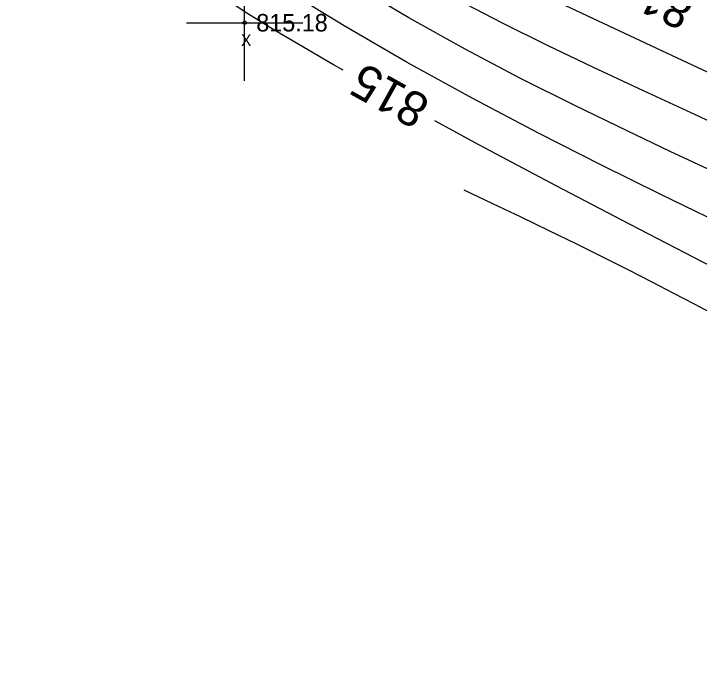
# Model space of a CAD drawing. Extents: x 1378535 to 1380697, y 997729 to 1000024.
# Drawn here: x 1379860 to 1379918.9, y 998571.5 to 998627.2 of the extents above; entities that cross this region are included whole.
import ezdxf

# ---------------------------------------------------------------- set-up
doc = ezdxf.new("R2010")
doc.units = 0
for name, color, linetype in [('RD_DTM_Major1', 7, 'Continuous'), ('RD_DTM_Major1_Lbl', 7, 'Continuous'), ('RD_DTM_Minor1', 7, 'Continuous'), ('RD_EX_Misc', 7, 'Continuous'), ('RD_EX_Misc_txCode', 7, 'Continuous'), ('RD_EX_TX_Misc_ELEV', 7, 'Continuous'), ('RD_SMD_Locator', 7, 'Continuous')]:
    doc.layers.add(name, color=color, linetype=linetype)

msp = doc.modelspace()

# ---------------------------------------------------------------- linework, layer by layer
at = {"layer": 'RD_DTM_Major1'}
for points in [[(1379888.299, 998622.362), (1379887.483, 998622.818), (1379882.346, 998625.829), (1379881.104, 998626.592), (1379879.945, 998627.322), (1379878.849, 998628.03), (1379877.798, 998628.726), (1379876.772, 998629.421), (1379875.752, 998630.124), (1379873.245, 998631.897), (1379870.675, 998633.765), (1379868.053, 998635.71), (1379865.393, 998637.713), (1379862.708, 998639.753), (1379860.01, 998641.813)], [(1379984.414, 998571.472), (1379984.005, 998571.536), (1379982.737, 998571.823), (1379981.492, 998572.144), (1379980.256, 998572.502), (1379979.016, 998572.902), (1379977.757, 998573.347), (1379976.466, 998573.841), (1379969.293, 998577.101), (1379961.379, 998581.317), (1379953.163, 998586.076), (1379945.086, 998590.961), (1379937.588, 998595.557), (1379931.108, 998599.448), (1379928.857, 998600.742), (1379926.767, 998601.902), (1379924.762, 998602.981), (1379922.764, 998604.028), (1379920.697, 998605.095), (1379918.483, 998606.233), (1379912.891, 998609.124), (1379906.6, 998612.417), (1379900.005, 998615.923), (1379896.173, 998618.003)]]:
    msp.add_lwpolyline(points, dxfattribs=at)
at = {"layer": 'RD_DTM_Minor1'}
for points in [[(1379920.029, 998613.667), (1379916.391, 998615.378), (1379912.69, 998617.129), (1379908.191, 998619.307), (1379903.548, 998621.639), (1379898.792, 998624.146), (1379893.95, 998626.85), (1379889.051, 998629.771)], [(1379921.428, 998608.835), (1379918.59, 998610.207), (1379915.595, 998611.661), (1379910.539, 998614.168), (1379905.084, 998616.951), (1379899.437, 998619.931), (1379893.805, 998623.027), (1379888.395, 998626.156), (1379883.415, 998629.238)], [(1379923.161, 998616.365), (1379918.579, 998618.51), (1379914.1, 998620.588), (1379909.752, 998622.614), (1379905.85, 998624.473), (1379901.99, 998626.391), (1379898.075, 998628.461)], [(1379922.67, 998620.75), (1379917.024, 998623.391), (1379911.59, 998625.925), (1379906.528, 998628.309)], [(1379920.203, 998601.322), (1379918.489, 998602.235), (1379916.702, 998603.178), (1379914.841, 998604.146), (1379912.906, 998605.136), (1379910.675, 998606.256), (1379908.369, 998607.394), (1379906.002, 998608.546), (1379903.59, 998609.71), (1379901.148, 998610.881), (1379898.691, 998612.056)]]:
    msp.add_lwpolyline(points, dxfattribs=at)
at = {"layer": 'RD_EX_Misc'}
for p, q in [((1379879.844, 998621.432), (1379879.844, 998631.432)), ((1379874.844, 998626.432), (1379884.844, 998626.432))]:
    msp.add_line(p, q, dxfattribs=at)
at = {"layer": 'RD_SMD_Locator'}
msp.add_circle((1379879.844, 998626.432), 0.15, dxfattribs=at)

# ---------------------------------------------------------------- texts
at = {"layer": 'RD_DTM_Major1_Lbl'}
for s, rotation, p in [('810', 154.76275, (1379918.65, 998628.409)), ('815', 151.03185, (1379895.929, 998619.83))]:
    msp.add_text(s, height=3, rotation=rotation, dxfattribs=at).set_placement(p)
at = {"layer": 'RD_EX_Misc_txCode'}
msp.add_text('X', height=1, dxfattribs=at).set_placement((1379879.529, 998624.432))
at = {"layer": 'RD_EX_TX_Misc_ELEV'}
msp.add_text('815.18', height=1.5, dxfattribs=at).set_placement((1379880.844, 998625.682))

doc.saveas('drawing.dxf')
